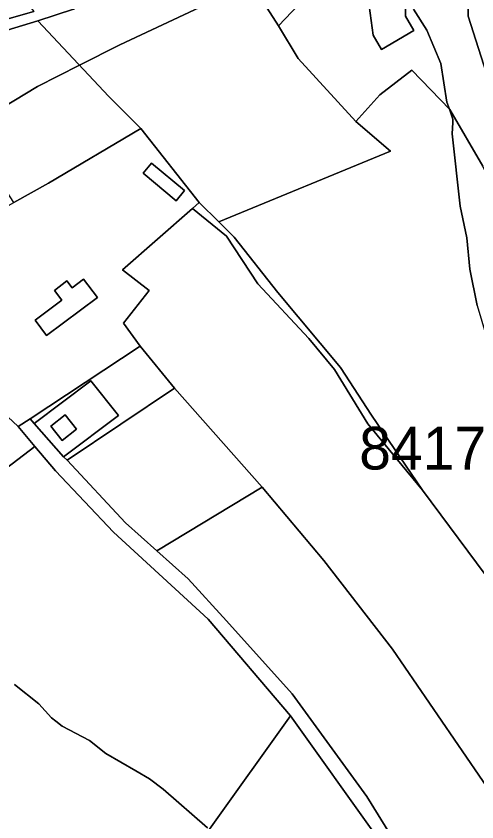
# Model space of a CAD drawing. Extents: x -477304 to -465429, y -1159113 to -1149210.
# Drawn here: x -471749.6 to -471587.7, y -1155674.2 to -1155391 of the extents above; entities that cross this region are included whole.
import ezdxf

# ---------------------------------------------------------------- set-up
doc = ezdxf.new("R2010")
doc.units = 0
for name, color, linetype in [('BPEJ_s', 7, 'Continuous'), ('orna_s', 7, 'Continuous'), ('ostatni_s', 7, 'Continuous'), ('trav_porost_s', 7, 'Continuous')]:
    doc.layers.add(name, color=color, linetype=linetype)

msp = doc.modelspace()

# ---------------------------------------------------------------- linework, layer by layer
at = {"layer": 'BPEJ_s'}
for points in [[(-471679.37, -1155385.16), (-471713.16, -1155401.1), (-471727.27, -1155408.26), (-471742.05, -1155415.76), (-471762.02, -1155427.87)], [(-471762.02, -1155427.87), (-471742.05, -1155415.76), (-471727.27, -1155408.26), (-471713.16, -1155401.1), (-471679.37, -1155385.16)], [(-471587.58, -1155492.68), (-471590.13, -1155479.93), (-471591.19, -1155468.88), (-471593.53, -1155457.83), (-471596.29, -1155432.33), (-471596.13, -1155428.45), (-471596.08, -1155427.23), (-471597.34, -1155423.7), (-471598.2, -1155421.28), (-471600.33, -1155407.69), (-471605.22, -1155396), (-471609.89, -1155388.56)], [(-471609.89, -1155388.56), (-471605.22, -1155396), (-471600.33, -1155407.69), (-471598.2, -1155421.28), (-471597.34, -1155423.7), (-471596.08, -1155427.23), (-471596.13, -1155428.45), (-471596.29, -1155432.33), (-471593.53, -1155457.83), (-471591.19, -1155468.88), (-471590.13, -1155479.93), (-471587.58, -1155492.68), (-471579.72, -1155519.03), (-471571.86, -1155536.02), (-471566.76, -1155544.52), (-471558.9, -1155556.42), (-471545.3, -1155572.57), (-471539.99, -1155581.92)], [(-471750.13, -1155625.9), (-471741.63, -1155632.7), (-471737.17, -1155637.59), (-471735.6, -1155638.81), (-471733.34, -1155640.56), (-471723.78, -1155645.66), (-471718.04, -1155650.12), (-471707.53, -1155656.26), (-471702.75, -1155659.05), (-471697.86, -1155662.66), (-471682.35, -1155676.26)], [(-471682.35, -1155676.26), (-471697.86, -1155662.66), (-471702.75, -1155659.05), (-471707.53, -1155656.26), (-471718.04, -1155650.12), (-471723.78, -1155645.66), (-471733.34, -1155640.56), (-471735.6, -1155638.81), (-471737.17, -1155637.59), (-471741.63, -1155632.7), (-471750.13, -1155625.9)]]:
    msp.add_lwpolyline(points, dxfattribs=at)
at = {"layer": 'orna_s'}
msp.add_lwpolyline([(-471742.93, -1155542.3), (-471773.94, -1155565.86), (-471787.38, -1155583.94), (-471791.66, -1155587.25), (-471794.54, -1155584.06), (-471809.98, -1155579.76), (-471821.24, -1155560.72), (-471833.9, -1155552.42), (-471772.95, -1155509.89), (-471763.21, -1155521.94), (-471748.81, -1155535.27)], close=True, dxfattribs=at)
at = {"layer": 'ostatni_s'}
for points in [[(-471643.88, -1155321.23), (-471654.3, -1155316.81), (-471642.95, -1155305.69), (-471635.2, -1155313.69), (-471654.39, -1155361.18), (-471645.61, -1155381.96), (-471657.42, -1155394.48), (-471675.6, -1155365.85), (-471675.65, -1155363.25), (-471668.04, -1155358.18), (-471667.55, -1155353.46), (-471662.8, -1155349.03), (-471662.55, -1155344.39)], [(-471625.84, -1155384.67), (-471618.16, -1155376.55), (-471612.71, -1155381.7), (-471612.69, -1155391.02), (-471609.76, -1155396.06), (-471621.19, -1155402.71), (-471624.12, -1155397.67)], [(-471690.34, -1155452.35), (-471693.3, -1155455.91), (-471704.96, -1155446.22), (-471702, -1155442.66)], [(-471624.66, -1155531.29), (-471606.72, -1155557.59), (-471626, -1155534.26), (-471637.71, -1155515.23), (-471646.72, -1155504.35), (-471664.67, -1155485.14), (-471675.66, -1155468.36), (-471687.56, -1155458.6), (-471685.19, -1155456.51), (-471678.3, -1155463.26), (-471672.95, -1155468.7), (-471657.58, -1155488.15), (-471635.58, -1155514.53)], [(-471729.9, -1155486.5), (-471725.88, -1155483.44), (-471720.98, -1155489.87), (-471738.85, -1155503.28), (-471742.91, -1155497.88), (-471733.52, -1155490.83), (-471736.13, -1155487.41), (-471731.75, -1155484.07)], [(-471733.36, -1155540.16), (-471737.34, -1155535.16), (-471732.35, -1155531.13), (-471728.32, -1155536.18)]]:
    msp.add_lwpolyline(points, close=True, dxfattribs=at)
for points in [[(-471582.55, -1155416.69), (-471590.76, -1155391.03), (-471590.38, -1155375.69)], [(-471729.44, -1155388.6), (-471741.94, -1155392.63), (-471758.2, -1155397.58), (-471784.02, -1155404.51), (-471796.18, -1155407.77), (-471816.46, -1155424.23), (-471821.9, -1155428.65), (-471827.9, -1155430.14), (-471856.23, -1155448.77), (-471870.77, -1155458.6), (-471888.24, -1155472.5), (-471893.31, -1155476.53), (-471909.21, -1155489.18), (-471919.93, -1155522.83), (-471924.8, -1155541.1)], [(-471924.12, -1155522.69), (-471922.43, -1155518.27), (-471912.57, -1155486.82), (-471895.03, -1155472.67), (-471877.68, -1155458.73), (-471854.87, -1155441.45), (-471823.25, -1155425.15), (-471797.27, -1155404.24), (-471763.64, -1155395.17), (-471743.37, -1155389.39)], [(-471553.26, -1155774.35), (-471592.2, -1155720.22), (-471610.1, -1155697.81), (-471623.01, -1155679.09), (-471653.18, -1155636.9), (-471682.03, -1155602.9), (-471715.35, -1155572.4), (-471735.78, -1155550.84), (-471742.93, -1155542.3), (-471748.81, -1155535.27), (-471744.67, -1155532.54), (-471743.18, -1155534.24), (-471732.89, -1155545.93), (-471731.68, -1155547.12), (-471711.14, -1155569.08), (-471700.11, -1155578.94), (-471689.08, -1155588.8), (-471675.61, -1155603.49), (-471652.59, -1155629.21), (-471626.32, -1155665.26), (-471608.54, -1155694.15), (-471579.11, -1155731.33)]]:
    msp.add_lwpolyline(points, dxfattribs=at)
at = {"layer": 'trav_porost_s'}
for points in [[(-471729.44, -1155388.6), (-471707.29, -1155374.99), (-471691.21, -1155356.26), (-471684.21, -1155351.53), (-471654.3, -1155316.81), (-471643.88, -1155321.23), (-471662.55, -1155344.39), (-471662.8, -1155349.03), (-471667.55, -1155353.46), (-471668.04, -1155358.18), (-471675.65, -1155363.25), (-471675.6, -1155365.85), (-471657.42, -1155394.48), (-471650.43, -1155405.94), (-471630.25, -1155428.03), (-471617.97, -1155438.48), (-471678.3, -1155463.26), (-471685.19, -1155456.51), (-471705.72, -1155430.49), (-471716.95, -1155419.26), (-471741.94, -1155392.63)], [(-471771.86, -1155353.74), (-471755.63, -1155374.05), (-471743.37, -1155389.39), (-471763.64, -1155395.17), (-471775.98, -1155356.16)], [(-471612.69, -1155391.02), (-471612.71, -1155381.7), (-471618.16, -1155376.55), (-471606.41, -1155364.14), (-471597.29, -1155360.03), (-471590.38, -1155375.69), (-471590.76, -1155391.03), (-471582.55, -1155416.69), (-471573.64, -1155430.2), (-471566.97, -1155452.56), (-471565.92, -1155476.99), (-471575.76, -1155465.24), (-471585.61, -1155443.78), (-471597.18, -1155423.87), (-471610.57, -1155410.01), (-471621.8, -1155418.62), (-471630.25, -1155428.03), (-471650.43, -1155405.94), (-471657.42, -1155394.48), (-471645.61, -1155381.96), (-471625.84, -1155384.67), (-471624.12, -1155397.67), (-471621.19, -1155402.71), (-471609.76, -1155396.06)], [(-471716.95, -1155419.26), (-471705.72, -1155430.49), (-471738.18, -1155449.74), (-471750.31, -1155456.52), (-471773.19, -1155421.22), (-471782.49, -1155406.87), (-471784.02, -1155404.51), (-471758.2, -1155397.58), (-471741.94, -1155392.63)], [(-471711.84, -1155498.87), (-471705.93, -1155506.99), (-471744.67, -1155532.54), (-471748.81, -1155535.27), (-471763.21, -1155521.94), (-471772.95, -1155509.89), (-471778.24, -1155503.13), (-471791.02, -1155484.43), (-471791.15, -1155484.24), (-471793.23, -1155483.81), (-471794.78, -1155481.4), (-471790.21, -1155478.84), (-471750.31, -1155456.52), (-471738.18, -1155449.74), (-471705.72, -1155430.49), (-471685.19, -1155456.51), (-471687.56, -1155458.6), (-471712.14, -1155480.18), (-471702.86, -1155487.48)], [(-471704.96, -1155446.22), (-471693.3, -1155455.91), (-471690.34, -1155452.35), (-471702, -1155442.66)], [(-471731.75, -1155484.07), (-471736.13, -1155487.41), (-471733.52, -1155490.83), (-471742.91, -1155497.88), (-471738.85, -1155503.28), (-471720.98, -1155489.87), (-471725.88, -1155483.44), (-471729.9, -1155486.5)], [(-471744.67, -1155532.54), (-471705.93, -1155506.99), (-471693.94, -1155521.72), (-471731.68, -1155547.12), (-471732.89, -1155545.93), (-471713.61, -1155531.33), (-471723.27, -1155519.21), (-471743.18, -1155534.24)], [(-471743.18, -1155534.24), (-471723.27, -1155519.21), (-471713.61, -1155531.33), (-471732.89, -1155545.93)], [(-471711.14, -1155569.08), (-471731.68, -1155547.12), (-471693.94, -1155521.72), (-471663.16, -1155556.57), (-471700.11, -1155578.94)], [(-471732.35, -1155531.13), (-471737.34, -1155535.16), (-471733.36, -1155540.16), (-471728.32, -1155536.18)], [(-471653.18, -1155636.9), (-471708.9, -1155714.99), (-471728.99, -1155696.58), (-471761.58, -1155675.35), (-471776.06, -1155657.66), (-471790.19, -1155642.16), (-471793.06, -1155615.39), (-471791.66, -1155587.25), (-471787.38, -1155583.94), (-471773.94, -1155565.86), (-471742.93, -1155542.3), (-471735.78, -1155550.84), (-471715.35, -1155572.4), (-471682.03, -1155602.9)], [(-471663.16, -1155556.57), (-471641.41, -1155582.3), (-471617.35, -1155613.54), (-471578.35, -1155670.41), (-471487.37, -1155786.67), (-471477.79, -1155803.85), (-471486.73, -1155801.03), (-471527.72, -1155803.63), (-471539.34, -1155785.86), (-471550.02, -1155774.19), (-471579.11, -1155731.33), (-471608.54, -1155694.15), (-471626.32, -1155665.26), (-471652.59, -1155629.21), (-471675.61, -1155603.49), (-471689.08, -1155588.8), (-471700.11, -1155578.94)], [(-471537.07, -1155793.86), (-471555.65, -1155811.59), (-471571.69, -1155801.25), (-471604.76, -1155787.69), (-471617.05, -1155777.53), (-471628.85, -1155761.45), (-471638.42, -1155744.11), (-471646.28, -1155734.9), (-471659.69, -1155725.16), (-471672.2, -1155719.74), (-471694.35, -1155721.39), (-471704.86, -1155718.28), (-471708.9, -1155714.99), (-471653.18, -1155636.9), (-471623.01, -1155679.09), (-471610.1, -1155697.81), (-471592.2, -1155720.22), (-471553.26, -1155774.35)]]:
    msp.add_lwpolyline(points, close=True, dxfattribs=at)
for points in [[(-471581.35, -1155591.79), (-471606.72, -1155557.59), (-471624.66, -1155531.29), (-471635.58, -1155514.53), (-471657.58, -1155488.15), (-471672.95, -1155468.7), (-471678.3, -1155463.26), (-471617.97, -1155438.48), (-471630.25, -1155428.03), (-471621.8, -1155418.62), (-471610.57, -1155410.01), (-471597.18, -1155423.87), (-471585.61, -1155443.78)], [(-471578.35, -1155670.41), (-471617.35, -1155613.54), (-471641.41, -1155582.3), (-471663.16, -1155556.57), (-471693.94, -1155521.72), (-471705.93, -1155506.99), (-471711.84, -1155498.87), (-471702.86, -1155487.48), (-471712.14, -1155480.18), (-471687.56, -1155458.6), (-471675.66, -1155468.36), (-471664.67, -1155485.14), (-471646.72, -1155504.35), (-471637.71, -1155515.23), (-471626, -1155534.26), (-471606.72, -1155557.59), (-471581.35, -1155591.79)]]:
    msp.add_lwpolyline(points, dxfattribs=at)

# ---------------------------------------------------------------- texts
at = {"layer": 'BPEJ_s'}
msp.add_text('84177/V.', height=15, dxfattribs=at).set_placement((-471629.02, -1155550.36))

doc.saveas('drawing.dxf')
